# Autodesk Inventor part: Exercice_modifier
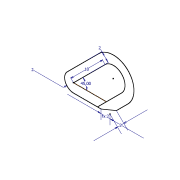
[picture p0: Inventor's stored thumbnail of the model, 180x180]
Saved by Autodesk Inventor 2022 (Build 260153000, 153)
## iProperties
Created: 2021-05
Part Number: Exercice_modifier
Material: Générique
Document SubType Name: Modeling
Designer: Fabian
Density: 1 g/cm^3
Appearance: Par défaut
Author: Fabian
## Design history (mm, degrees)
sketch "Esquisse1"
  geometry: L1 (0, 0)-(7.071, 7.071); L2 (0, 0)-(7.352, 0); L3 (10.747, 3.395)-(5.352, -2); L4 (7.352, 0)-(0, 0); L5 (5.657, 8.485)-(-1.414, 1.414); L6 (0, -2)-(6.18, -2); L7 (9.594, -0.586)-(12.161, 1.981); L8 (9.594, -0.586)-(6.18, -2); A1 r 2.599 centre (8.909, 5.233) between (10.747, 3.395) and (7.071, 7.071); A2 r 4.599 centre (8.909, 5.233) between (12.161, 1.981) and (5.657, 8.485); A3 r 2 centre (0, 0) between (-1.414, 1.414) and (0, -2); 1 further point
  constraints: 16 end point, 6 point on circle, 4 point on line, 4 tangent, 3 centre point, 2 horizontal, 2 parallel, 1 other
  dimensions: "d26" = 10 distance of L1.start L1.end; "d27" = 45 deg angle of L2 L1; "d28" = 2 distance between parallel lines of L1 L5; "d29" = 2 radius of A3; "d30" = 2 distance of L7.start point (8.18, -2); "d31" = 2 distance of L6.end point (8.18, -2) (= d30)
node "Solide1"
